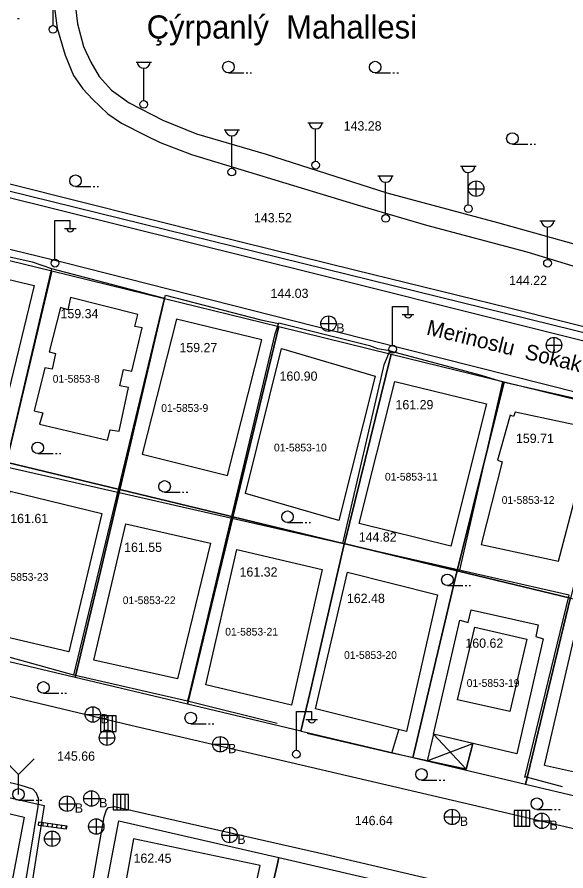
# Model space of a CAD drawing. Extents: x 419101 to 420177, y 4451541 to 4452254.
# Drawn here: x 419281.2 to 419352.3, y 4451782.3 to 4451893 of the extents above; entities that cross this region are included whole.
import ezdxf

# ---------------------------------------------------------------- set-up
doc = ezdxf.new("R2010")
doc.units = 0
doc.layers.add('2_KADASTRO', color=7, linetype='Continuous')
doc.layers.add('3_HALİHAZIR', color=7, linetype='Continuous')

msp = doc.modelspace()

# ---------------------------------------------------------------- linework, layer by layer
at = {"layer": '2_KADASTRO'}
for points in [[(419523.25, 4451817.52), (419440.11, 4451831.22), (419423.43, 4451835.17), (419425.53, 4451844.36), (419417.12, 4451845.49), (419416.03, 4451836.87), (419415, 4451837.13), (419412.52, 4451837.75), (419400.55, 4451840.78), (419218.08, 4451885.76), (419210.69, 4451887.97), (419201.62, 4451892.03), (419189.13, 4451898.23)], [(419262.42, 4451763.36), (419265.98, 4451778.63), (419269.62, 4451794.25), (419284.72, 4451790.82), (419280.41, 4451763.36)]]:
    msp.add_lwpolyline(points, dxfattribs=at)
for points in [[(419265.28, 4451838.83), (419271.01, 4451863.73), (419285.72, 4451860.12), (419279.86, 4451835.32)], [(419279.86, 4451835.32), (419285.72, 4451860.12), (419300.29, 4451856.54), (419294.54, 4451831.78), (419294.48, 4451831.79), (419279.98, 4451835.29)], [(419294.54, 4451831.78), (419300.29, 4451856.54), (419315.1, 4451852.91), (419309.17, 4451828.25), (419308.47, 4451828.42)], [(419309.17, 4451828.25), (419315.1, 4451852.91), (419329.67, 4451849.33), (419323.61, 4451824.76)], [(419323.61, 4451824.76), (419329.67, 4451849.33), (419344.28, 4451845.75), (419338.19, 4451821.25), (419323.7, 4451824.74)], [(419338.19, 4451821.25), (419344.28, 4451845.75), (419359.05, 4451842.12), (419352.87, 4451817.71), (419338.36, 4451821.21)], [(419274.14, 4451810.86), (419279.79, 4451834.98), (419279.86, 4451835.32), (419279.98, 4451835.29), (419294.48, 4451831.79), (419294.54, 4451831.78), (419294.5, 4451831.6), (419292.01, 4451821.16), (419288.73, 4451807.4)], [(419288.73, 4451807.4), (419292.01, 4451821.16), (419294.5, 4451831.6), (419294.54, 4451831.78), (419308.47, 4451828.42), (419309.17, 4451828.25), (419309.17, 4451828.21), (419303.28, 4451803.95)], [(419303.28, 4451803.95), (419309.17, 4451828.21), (419309.17, 4451828.25), (419323.61, 4451824.76), (419323.55, 4451824.51), (419319.11, 4451805.35), (419317.97, 4451800.46)], [(419317.97, 4451800.46), (419319.11, 4451805.35), (419323.55, 4451824.51), (419323.61, 4451824.76), (419323.7, 4451824.74), (419338.19, 4451821.25), (419338.08, 4451820.78), (419332.47, 4451797.02), (419318.06, 4451800.44)], [(419332.47, 4451797.02), (419338.08, 4451820.78), (419338.19, 4451821.25), (419338.36, 4451821.21), (419352.87, 4451817.71), (419352.85, 4451817.62), (419347.07, 4451793.56)], [(419347.07, 4451793.56), (419352.85, 4451817.62), (419352.87, 4451817.71), (419367.66, 4451814.14), (419361.66, 4451790.1)], [(419291.33, 4451772.78), (419294.38, 4451788.86), (419315.12, 4451784.07), (419314.89, 4451783.09), (419311.45, 4451768.23), (419311.07, 4451768.31), (419299.49, 4451770.93), (419292.9, 4451772.42)], [(419311.45, 4451768.23), (419314.89, 4451783.09), (419315.12, 4451784.07), (419336.55, 4451779.12), (419336.25, 4451777.82), (419332.91, 4451763.37)]]:
    msp.add_lwpolyline(points, close=True, dxfattribs=at)
at = {"layer": '3_HALİHAZIR'}
for p, q in [((419285.87, 4451891.91), (419285.87, 4451896.1)), ((419281.28, 4451892.84), (419281.48, 4451892.84)), ((419296.62, 4451887.19), (419298.62, 4451887.19)), ((419297.62, 4451882.19), (419297.62, 4451886.39)), ((419308.58, 4451885.79), (419310.58, 4451885.79)), ((419310.88, 4451885.79), (419311.08, 4451885.79)), ((419311.38, 4451885.79), (419311.58, 4451885.79)), ((419327.59, 4451885.78), (419329.59, 4451885.78)), ((419329.89, 4451885.78), (419330.09, 4451885.78)), ((419330.39, 4451885.78), (419330.59, 4451885.78)), ((419318.87, 4451879.32), (419320.87, 4451879.32)), ((419308.02, 4451878.42), (419310.02, 4451878.42)), ((419309.02, 4451873.42), (419309.02, 4451877.62)), ((419319.87, 4451874.32), (419319.87, 4451878.51)), ((419345.36, 4451876.52), (419347.36, 4451876.52)), ((419347.66, 4451876.52), (419347.86, 4451876.52)), ((419348.16, 4451876.52), (419348.36, 4451876.52)), ((419338.65, 4451873.68), (419340.65, 4451873.68)), ((419327.94, 4451872.42), (419329.94, 4451872.42)), ((419339.65, 4451868.68), (419339.65, 4451872.87)), ((419288.78, 4451871.05), (419290.78, 4451871.05)), ((419291.08, 4451871.05), (419291.28, 4451871.05)), ((419291.58, 4451871.05), (419291.78, 4451871.05)), ((419328.94, 4451867.42), (419328.94, 4451871.62)), ((419340.67, 4451869.77), (419340.67, 4451871.77)), ((419339.65, 4451870.76), (419341.65, 4451870.76)), ((419286.11, 4451861.65), (419286.11, 4451866.65)), ((419286.11, 4451866.65), (419288.11, 4451866.65)), ((419288.11, 4451865.65), (419288.11, 4451866.65)), ((419348.91, 4451866.61), (419350.91, 4451866.61)), ((419287.35, 4451865.61), (419288.85, 4451865.61)), ((419349.91, 4451861.61), (419349.91, 4451865.81)), ((419329.85, 4451850.5), (419329.85, 4451855.5)), ((419329.85, 4451855.5), (419331.85, 4451855.5)), ((419331.85, 4451854.5), (419331.85, 4451855.5)), ((419331.09, 4451854.46), (419332.59, 4451854.46)), ((419320.55, 4451853.28), (419322.55, 4451853.28)), ((419321.55, 4451854.28), (419321.55, 4451852.28)), ((419350.75, 4451849.49), (419350.75, 4451851.49)), ((419349.73, 4451850.48), (419351.73, 4451850.48)), ((419283.89, 4451836.43), (419285.89, 4451836.43)), ((419286.19, 4451836.43), (419286.39, 4451836.43)), ((419286.69, 4451836.43), (419286.89, 4451836.43)), ((419300.32, 4451831.43), (419302.32, 4451831.43)), ((419302.62, 4451831.43), (419302.82, 4451831.43)), ((419303.12, 4451831.43), (419303.32, 4451831.43)), ((419316.23, 4451827.5), (419318.23, 4451827.5)), ((419318.53, 4451827.5), (419318.73, 4451827.5)), ((419319.03, 4451827.5), (419319.23, 4451827.5)), ((419336.94, 4451819.33), (419338.94, 4451819.33)), ((419339.24, 4451819.33), (419339.44, 4451819.33)), ((419339.74, 4451819.33), (419339.94, 4451819.33)), ((419284.62, 4451805.38), (419286.62, 4451805.38)), ((419286.92, 4451805.38), (419287.12, 4451805.38)), ((419287.42, 4451805.38), (419287.62, 4451805.38)), ((419291.03, 4451803.63), (419291.03, 4451801.63)), ((419290.03, 4451802.63), (419292.03, 4451802.63)), ((419294.03, 4451802.44), (419292.03, 4451802.44)), ((419292.03, 4451802.44), (419292.03, 4451800.44)), ((419294.03, 4451802.44), (419292.03, 4451802.44)), ((419292.03, 4451802.44), (419292.03, 4451800.44)), ((419292.53, 4451800.44), (419292.53, 4451802.44)), ((419293.03, 4451800.44), (419293.03, 4451802.44)), ((419293.58, 4451800.44), (419293.58, 4451802.44)), ((419294.03, 4451800.44), (419294.03, 4451802.44)), ((419294.03, 4451800.44), (419294.03, 4451802.44)), ((419317.38, 4451798.01), (419317.38, 4451803.01)), ((419317.38, 4451803.01), (419319.38, 4451803.01)), ((419319.38, 4451802.01), (419319.38, 4451803.01)), ((419303.7, 4451801.41), (419305.7, 4451801.41)), ((419306, 4451801.41), (419306.2, 4451801.41)), ((419306.5, 4451801.41), (419306.7, 4451801.41)), ((419318.62, 4451801.97), (419320.12, 4451801.97)), ((419292.03, 4451800.44), (419294.03, 4451800.44)), ((419292.03, 4451800.44), (419294.03, 4451800.44)), ((419292.88, 4451798.61), (419292.88, 4451800.61)), ((419291.86, 4451799.6), (419293.86, 4451799.6)), ((419307.53, 4451799.77), (419307.53, 4451797.77)), ((419306.53, 4451798.77), (419308.53, 4451798.77)), ((419281.4, 4451794.86), (419279.4, 4451796.86)), ((419281.4, 4451794.86), (419283.41, 4451796.86)), ((419281.4, 4451792.27), (419281.4, 4451794.86)), ((419333.59, 4451794.11), (419335.59, 4451794.11)), ((419335.89, 4451794.11), (419336.09, 4451794.11)), ((419336.39, 4451794.11), (419336.59, 4451794.11)), ((419290.84, 4451792.74), (419290.84, 4451790.74)), ((419281.4, 4451791.52), (419283.4, 4451791.52)), ((419283.7, 4451791.52), (419283.9, 4451791.52)), ((419284.2, 4451791.52), (419284.4, 4451791.52)), ((419287.69, 4451792.06), (419287.69, 4451790.06)), ((419289.84, 4451791.74), (419291.84, 4451791.74)), ((419295.66, 4451792.25), (419293.66, 4451792.25)), ((419293.66, 4451792.25), (419293.66, 4451790.25)), ((419295.66, 4451792.25), (419293.66, 4451792.25)), ((419293.66, 4451792.25), (419293.66, 4451790.25)), ((419294.16, 4451790.25), (419294.16, 4451792.25)), ((419294.66, 4451790.25), (419294.66, 4451792.25)), ((419295.21, 4451790.25), (419295.21, 4451792.25)), ((419295.66, 4451790.25), (419295.66, 4451792.25)), ((419295.66, 4451790.25), (419295.66, 4451792.25)), ((419286.69, 4451791.06), (419288.69, 4451791.06)), ((419293.66, 4451790.25), (419295.66, 4451790.25)), ((419293.66, 4451790.25), (419295.66, 4451790.25)), ((419337.55, 4451790.35), (419337.55, 4451788.35)), ((419347.6, 4451790.16), (419345.6, 4451790.16)), ((419345.6, 4451790.16), (419345.6, 4451788.16)), ((419347.6, 4451790.16), (419345.6, 4451790.16)), ((419345.6, 4451790.16), (419345.6, 4451788.16)), ((419346.1, 4451788.16), (419346.1, 4451790.16)), ((419346.6, 4451788.16), (419346.6, 4451790.16)), ((419347.14, 4451788.16), (419347.14, 4451790.16)), ((419347.6, 4451788.16), (419347.6, 4451790.16)), ((419347.6, 4451788.16), (419347.6, 4451790.16)), ((419348.53, 4451790.31), (419350.53, 4451790.31)), ((419350.83, 4451790.31), (419351.03, 4451790.31)), ((419351.33, 4451790.31), (419351.53, 4451790.31)), ((419291.48, 4451787.09), (419291.48, 4451789.09)), ((419336.55, 4451789.35), (419338.55, 4451789.35)), ((419349.16, 4451789.84), (419349.16, 4451787.84)), ((419283.98, 4451788.25), (419284.04, 4451788.71)), ((419284.57, 4451788.17), (419284.64, 4451788.63)), ((419285.17, 4451788.09), (419285.23, 4451788.54)), ((419285.76, 4451788.01), (419285.83, 4451788.46)), ((419286.36, 4451787.93), (419286.42, 4451788.37)), ((419286.95, 4451787.85), (419287.01, 4451788.29)), ((419287.55, 4451787.77), (419287.61, 4451788.21)), ((419290.46, 4451788.08), (419292.46, 4451788.08)), ((419308.74, 4451788), (419308.74, 4451786)), ((419345.6, 4451788.16), (419347.6, 4451788.16)), ((419345.6, 4451788.16), (419347.6, 4451788.16)), ((419348.16, 4451788.84), (419350.16, 4451788.84)), ((419285.78, 4451785.51), (419285.78, 4451787.51)), ((419307.74, 4451787), (419309.74, 4451787)), ((419284.76, 4451786.5), (419286.76, 4451786.5))]:
    msp.add_line(p, q, dxfattribs=at)
for points in [[(419197.14, 4451918.49), (419190.3, 4451906.14), (419187.84, 4451901.73), (419187.33, 4451900.47), (419187.22, 4451899.82), (419187.2, 4451899.12), (419187.52, 4451898.4), (419188.02, 4451898.02), (419206.05, 4451888.79), (419207.67, 4451888.15), (419211.14, 4451887.04), (419263.32, 4451873.84), (419278.61, 4451870.01), (419319.77, 4451859.79), (419370.79, 4451846.97), (419405.26, 4451838.47), (419438.95, 4451830.41), (419524.68, 4451816.03), (419556.86, 4451810.45)], [(419189.98, 4451898.51), (419196.68, 4451895.25), (419205.35, 4451890.37), (419206.11, 4451890.06), (419208.05, 4451889.62), (419220.91, 4451886.35), (419241.42, 4451881.31), (419263.19, 4451875.75), (419280.47, 4451871.35), (419306.58, 4451864.81), (419324.9, 4451860.26), (419344.99, 4451855.34)], [(419288.63, 4451898.19), (419288.64, 4451895.41), (419289.02, 4451892.13), (419289.81, 4451889.21), (419290.76, 4451887.19), (419291.83, 4451885.32), (419293.46, 4451883.53), (419295.74, 4451881.91), (419300.07, 4451879.65), (419304.43, 4451877.86), (419313.47, 4451875.25), (419329.08, 4451870.25), (419343.44, 4451866.38), (419356.24, 4451862.8), (419370.6, 4451858.13), (419372.42, 4451857.56), (419382.3, 4451855.13), (419387.6, 4451854.09), (419392.41, 4451853.74), (419397.49, 4451853.63), (419404.63, 4451853.57), (419407.38, 4451853.5), (419408.05, 4451853.42)], [(419285.93, 4451895.18), (419286.39, 4451891.58), (419287.45, 4451888.08), (419288.54, 4451885.46), (419289.73, 4451883.7), (419290.97, 4451882.36), (419292.95, 4451880.49), (419294.74, 4451879.27), (419297.87, 4451877.65), (419299.73, 4451876.74), (419303.81, 4451875.22), (419311.19, 4451872.96), (419325.26, 4451868.67), (419334.22, 4451866.06), (419347.24, 4451862.57), (419361.11, 4451858.35)], [(419272.23, 4451806.89), (419295.94, 4451801.22), (419314.11, 4451797.01), (419341.49, 4451790.62), (419373.23, 4451783.2), (419387.02, 4451779.9), (419394.29, 4451778.28), (419395.41, 4451778.07), (419397.15, 4451778.38), (419398.38, 4451779.65), (419398.98, 4451780.72), (419400.65, 4451793.92), (419404.79, 4451827.5), (419404.58, 4451829.02), (419404.24, 4451829.88), (419403.83, 4451830.4), (419403.33, 4451830.64), (419367.67, 4451840.81), (419322.38, 4451852.27), (419287.54, 4451861.1), (419239.64, 4451872.77)], [(419271.31, 4451863.93), (419283.17, 4451861.3)], [(419283.17, 4451861.3), (419285.66, 4451860.41)], [(419285.66, 4451860.41), (419274.22, 4451811.71), (419268.22, 4451812.98)], [(419285.66, 4451860.41), (419297.66, 4451857.26)], [(419297.66, 4451857.26), (419300.35, 4451856.6)], [(419300.19, 4451856.04), (419300.45, 4451856.98), (419312.79, 4451853.79)], [(419288.55, 4451807.72), (419300.19, 4451856.04)], [(419344.99, 4451855.34), (419373.46, 4451848.17), (419400.75, 4451841.16)], [(419312.79, 4451853.79), (419315.06, 4451853.28)], [(419314.64, 4451851.98), (419315.1, 4451853.4), (419326.87, 4451850.44)], [(419303.47, 4451804.85), (419314.64, 4451851.98)], [(419326.87, 4451850.44), (419327.88, 4451850.07)], [(419327.88, 4451850.07), (419329.49, 4451849.79), (419328.8, 4451848.1)], [(419329.48, 4451849.77), (419341.3, 4451846.62)], [(419323.41, 4451824.77), (419328.8, 4451848.1)], [(419341.3, 4451846.62), (419344.12, 4451845.72)], [(419338.55, 4451821.32), (419344.12, 4451845.72)], [(419344.12, 4451845.72), (419356.11, 4451843)], [(419352.73, 4451818.1), (419279.63, 4451834.74)], [(419346.99, 4451794.46), (419352.73, 4451818.1)], [(419288.55, 4451807.72), (419274.04, 4451811.75)], [(419303.3, 4451804.36), (419288.55, 4451807.72)], [(419314.89, 4451801.46), (419303.3, 4451804.36), (419303.47, 4451804.85)], [(419279.44, 4451763.36), (419283.94, 4451790.7), (419284.03, 4451791.62), (419283.75, 4451792.43), (419283.25, 4451792.93), (419281.75, 4451793.44), (419244.87, 4451802.46)], [(419329.75, 4451797.62), (419318.78, 4451800.14)], [(419340.25, 4451798.87), (419339.38, 4451795.54), (419329.75, 4451797.62), (419330.67, 4451800.65)], [(419335.14, 4451800.07), (419339.38, 4451795.54)], [(419334.33, 4451796.63), (419340.25, 4451798.87)], [(419351.85, 4451793.24), (419347, 4451794.53)], [(419275.71, 4451763.36), (419264.59, 4451765.86), (419265.97, 4451772.3), (419266.6, 4451772.1), (419267.55, 4451776.43), (419266.86, 4451776.54), (419267.99, 4451781.73), (419268.67, 4451781.58), (419269.68, 4451786.02), (419269, 4451786.13), (419270.45, 4451792.08), (419282.13, 4451789.32), (419277.17, 4451763.36)], [(419288.1, 4451763.36), (419289.32, 4451771.08), (419292.5, 4451789.35), (419292.8, 4451790.28), (419293.05, 4451790.56), (419293.84, 4451790.72), (419321.05, 4451784.54), (419379.34, 4451770.85), (419379.37, 4451770.85), (419379.76, 4451770.6), (419380.02, 4451770.25), (419380.31, 4451769.46), (419380.35, 4451768.57), (419380.31, 4451768.06), (419379.98, 4451766.57), (419378.93, 4451763.36)]]:
    msp.add_lwpolyline(points, dxfattribs=at)
for points in [[(419268.18, 4451842.62), (419272.45, 4451860.82), (419283.43, 4451858.24), (419279.13, 4451840.4)], [(419284.12, 4451840.25), (419292.91, 4451838.19), (419293.26, 4451839.53), (419294.43, 4451839.34), (419295.65, 4451844.99), (419294.53, 4451845.2), (419294.99, 4451847.33), (419296.09, 4451847.12), (419297.43, 4451852.72), (419296.46, 4451852.9), (419296.87, 4451854.45), (419288.13, 4451856.66), (419287.79, 4451855.09), (419286.82, 4451855.39), (419285.38, 4451849.63), (419286.21, 4451849.4), (419285.77, 4451847.38), (419284.8, 4451847.55), (419283.42, 4451841.97), (419284.56, 4451841.7)], [(419308.45, 4451833.6), (419312.89, 4451851.17), (419301.88, 4451853.87), (419297.42, 4451836.37)], [(419310.78, 4451831.25), (419315.45, 4451850.07), (419327.57, 4451846.48), (419322.87, 4451827.76)], [(419325.53, 4451827.39), (419330.15, 4451845.78), (419342.01, 4451842.9), (419337.38, 4451824.46)], [(419341.31, 4451824.67), (419351.34, 4451822.5), (419354.17, 4451833.32), (419354.7, 4451833.26), (419356.13, 4451839.07), (419355.73, 4451839.13), (419355.86, 4451839.65), (419345.7, 4451841.82), (419345.48, 4451841.26), (419345.07, 4451841.4), (419343.42, 4451835.58), (419344.03, 4451835.38)], [(419275.98, 4451813.55), (419280.33, 4451831.56), (419292.21, 4451828.69), (419287.91, 4451810.73)], [(419291.17, 4451809.67), (419295.3, 4451827.34), (419306.25, 4451824.81), (419302.01, 4451807.24)], [(419305.66, 4451806.46), (419309.68, 4451824), (419320.74, 4451821.41), (419316.77, 4451803.82)], [(419319.85, 4451803.35), (419323.99, 4451821.07), (419335.68, 4451818.14), (419331.63, 4451800.41)], [(419335.14, 4451800.07), (419338.55, 4451814.84), (419339.65, 4451814.54), (419340.01, 4451816.19), (419348.71, 4451814.24), (419348.4, 4451812.72), (419349.36, 4451812.43), (419345.95, 4451797.53)], [(419338.26, 4451804.52), (419340.5, 4451813.95), (419347.21, 4451812.4), (419345.01, 4451802.99)], [(419349.5, 4451796.01), (419353.58, 4451813.5), (419364.44, 4451810.94), (419360.41, 4451793.6)], [(419335.14, 4451800.07), (419334.33, 4451796.63), (419339.38, 4451795.54), (419340.25, 4451798.87)], [(419283.98, 4451788.25), (419284.04, 4451788.71), (419287.65, 4451788.2), (419287.59, 4451787.77)], [(419294.29, 4451775.4), (419310.22, 4451771.91), (419312.71, 4451783.05), (419296.31, 4451786.53)]]:
    msp.add_lwpolyline(points, close=True, dxfattribs=at)
for centre, radius in [((419285.87, 4451891.41), 0.5), ((419308.58, 4451886.54), 0.75), ((419327.59, 4451886.53), 0.75), ((419297.62, 4451881.69), 0.5), ((419345.36, 4451877.27), 0.75), ((419319.87, 4451873.82), 0.5), ((419309.02, 4451872.92), 0.5), ((419288.78, 4451871.8), 0.75), ((419340.66, 4451870.78), 1), ((419339.65, 4451868.18), 0.5), ((419328.94, 4451866.92), 0.5), ((419286.12, 4451861.12), 0.5), ((419349.91, 4451861.11), 0.5), ((419321.55, 4451853.28), 1), ((419350.74, 4451850.5), 1), ((419329.86, 4451849.97), 0.5), ((419283.89, 4451837.18), 0.75), ((419300.32, 4451832.18), 0.75), ((419316.23, 4451828.25), 0.75), ((419336.94, 4451820.08), 0.75), ((419284.62, 4451806.13), 0.75), ((419291.03, 4451802.63), 1), ((419303.7, 4451802.16), 0.75), ((419292.86, 4451799.61), 1), ((419307.53, 4451798.77), 1), ((419317.39, 4451797.48), 0.5), ((419333.59, 4451794.86), 0.75), ((419281.4, 4451792.27), 0.75), ((419290.84, 4451791.74), 1), ((419287.69, 4451791.06), 1), ((419348.53, 4451791.06), 0.75), ((419337.55, 4451789.35), 1), ((419291.47, 4451788.1), 1), ((419349.16, 4451788.84), 1), ((419308.74, 4451787), 1), ((419285.76, 4451786.52), 1)]:
    msp.add_circle(centre, radius, dxfattribs=at)
for centre, radius, start, end in [((419297.62, 4451887.22), 0.837, 183.298, 356.9072), ((419319.87, 4451879.35), 0.837, 183.298, 356.9072), ((419309.02, 4451878.45), 0.837, 183.298, 356.9072), ((419339.65, 4451873.71), 0.837, 183.298, 356.9072), ((419328.94, 4451872.45), 0.837, 183.298, 356.9072), ((419349.91, 4451866.64), 0.837, 183.298, 356.9072), ((419288.11, 4451865.65), 0.474, 184.8384, 355.1464), ((419331.85, 4451854.5), 0.474, 184.8384, 355.1464), ((419319.38, 4451802.01), 0.474, 184.8384, 355.1464)]:
    msp.add_arc(centre, radius, start, end, dxfattribs=at)

# ---------------------------------------------------------------- texts
at = {"layer": '2_KADASTRO'}
for s, p in [('01-5853-8', (419285.83, 4451845.63)), ('01-5853-9', (419299.88, 4451841.85)), ('01-5853-10', (419314.48, 4451836.72)), ('01-5853-11', (419328.85, 4451832.94)), ('01-5853-12', (419343.97, 4451829.92)), ('01-5853-23', (419278.43, 4451819.95)), ('01-5853-22', (419294.9, 4451816.93)), ('01-5853-21', (419308.17, 4451812.85)), ('01-5853-20', (419323.56, 4451809.83)), ('01-5853-19', (419339.44, 4451806.2))]:
    msp.add_text(s, height=1, dxfattribs=at).set_placement(p)
at = {"layer": '3_HALİHAZIR'}
for s, height, p in [('Çýrpanlý  Mahallesi', 3, (419298, 4451890.23)), ('159.34', 1.2, (419286.84, 4451853.98)), ('B', 1.2, (419322.55, 4451852.12)), ('159.27', 1.2, (419302.24, 4451849.58)), ('160.90', 1.2, (419315.21, 4451845.88)), ('161.29', 1.2, (419330.22, 4451842.18)), ('159.71', 1.2, (419345.82, 4451837.81)), ('161.61', 1.2, (419280.33, 4451827.43)), ('161.55', 1.2, (419295.08, 4451823.7)), ('161.32', 1.2, (419310.03, 4451820.5)), ('162.48', 1.2, (419323.93, 4451817.09)), ('160.62', 1.2, (419339.27, 4451811.27)), ('B', 1.2, (419292.03, 4451801.47)), ('B', 1.2, (419308.53, 4451797.61)), ('B', 1.2, (419291.84, 4451790.58)), ('B', 1.2, (419288.69, 4451789.9)), ('B', 1.2, (419338.55, 4451788.19)), ('B', 1.2, (419350.16, 4451787.68)), ('B', 1.2, (419309.74, 4451785.84)), ('162.45 ', 1.2, (419296.3, 4451783.4))]:
    msp.add_text(s, height=height, dxfattribs=at).set_placement(p)
for s, height, rotation, p in [('143.28 ', 1.2, 359.998, (419323.51, 4451878.31)), ('143.52 ', 1.2, 359.998, (419311.89, 4451866.4)), ('144.22 ', 1.2, 359.998, (419344.93, 4451858.28)), ('144.03 ', 1.2, 359.998, (419314.04, 4451856.61)), ('Merinoslu  Sokak', 2, 346.1421, (419334.12, 4451851.89)), ('144.82 ', 1.2, 359.998, (419325.46, 4451825.03)), ('145.66 ', 1.2, 359.998, (419286.4, 4451796.63)), ('146.64 ', 1.2, 359.998, (419324.96, 4451788.28))]:
    msp.add_text(s, height=height, rotation=rotation, dxfattribs=at).set_placement(p)

doc.saveas('drawing.dxf')
